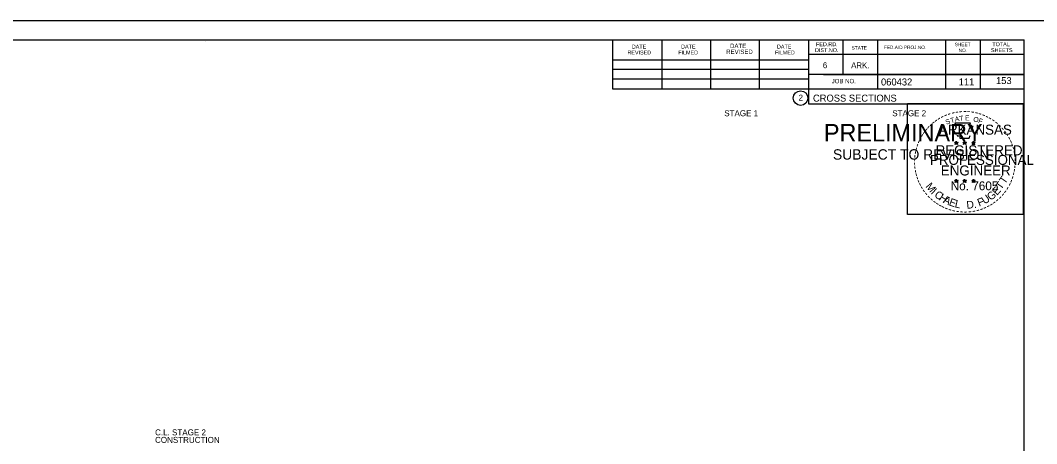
# Model space of a CAD drawing. Extents: x 1538688 to 1540766, y 656250 to 671912.
# Drawn here: x 1538815.6 to 1539018.9, y 664146.7 to 664231.4 of the extents above; entities that cross this region are included whole.
import ezdxf

# ---------------------------------------------------------------- set-up
doc = ezdxf.new("R2010")
doc.units = 0
for name, color, linetype in [('26', 7, 'Continuous'), ('7', 7, 'Continuous'), ('8', 7, 'Continuous'), ('9', 7, 'Continuous'), ('Default', 7, 'Continuous'), ('RipRap', 7, 'Continuous')]:
    doc.layers.add(name, color=color, linetype=linetype)

msp = doc.modelspace()

# ---------------------------------------------------------------- linework, layer by layer
at = {"layer": '26'}
msp.add_line((1538687.78, 664231.4), (1539021.11, 664231.4), dxfattribs=at)
for points in [[(1538687.77, 664231.4), (1539021.11, 664231.4), (1539021.11, 664018.07), (1538687.77, 664018.07)], [(1538993.03, 664214.74), (1539016.13, 664214.74), (1539016.13, 664192.59), (1538993.03, 664192.59)]]:
    msp.add_lwpolyline(points, close=True, dxfattribs=at)
at = {"layer": '8'}
for p, q in [((1539002.44, 664206.95), (1539002.79, 664206.84)), ((1539002.44, 664206.95), (1539002.69, 664206.91)), ((1539002.44, 664206.95), (1539002.68, 664206.83)), ((1539002.57, 664206.55), (1539002.79, 664206.84)), ((1539002.57, 664206.55), (1539002.7, 664206.79)), ((1539002.57, 664206.55), (1539002.79, 664206.76)), ((1539002.79, 664207.21), (1539002.75, 664206.96)), ((1539002.79, 664206.84), (1539002.79, 664207.21)), ((1539002.79, 664207.21), (1539002.84, 664206.96)), ((1539003.13, 664206.95), (1539002.79, 664206.84)), ((1539003, 664206.55), (1539002.79, 664206.84)), ((1539003, 664206.55), (1539002.79, 664206.76)), ((1539003.13, 664206.95), (1539002.85, 664206.91)), ((1539003, 664206.55), (1539002.86, 664206.84)), ((1539003.13, 664206.95), (1539002.93, 664206.85)), ((1539004.11, 664206.95), (1539004.46, 664206.84)), ((1539004.11, 664206.95), (1539004.36, 664206.91)), ((1539004.11, 664206.95), (1539004.35, 664206.83)), ((1539004.24, 664206.55), (1539004.46, 664206.84)), ((1539004.24, 664206.55), (1539004.37, 664206.79)), ((1539004.24, 664206.55), (1539004.46, 664206.76)), ((1539004.46, 664207.21), (1539004.42, 664206.96)), ((1539004.46, 664206.84), (1539004.46, 664207.21)), ((1539004.46, 664207.21), (1539004.51, 664206.96)), ((1539004.8, 664206.95), (1539004.46, 664206.84)), ((1539004.67, 664206.55), (1539004.46, 664206.84)), ((1539004.67, 664206.55), (1539004.46, 664206.76)), ((1539004.8, 664206.95), (1539004.52, 664206.91)), ((1539004.67, 664206.55), (1539004.53, 664206.84)), ((1539004.8, 664206.95), (1539004.6, 664206.85)), ((1539005.87, 664206.94), (1539006.22, 664206.83)), ((1539005.87, 664206.94), (1539006.13, 664206.9)), ((1539005.87, 664206.94), (1539006.11, 664206.82)), ((1539006.01, 664206.53), (1539006.22, 664206.83)), ((1539006.01, 664206.53), (1539006.13, 664206.78)), ((1539006.01, 664206.53), (1539006.22, 664206.75)), ((1539006.22, 664207.2), (1539006.18, 664206.94)), ((1539006.22, 664206.83), (1539006.22, 664207.2)), ((1539006.22, 664207.2), (1539006.27, 664206.95)), ((1539006.57, 664206.94), (1539006.22, 664206.83)), ((1539006.43, 664206.53), (1539006.22, 664206.83)), ((1539006.43, 664206.53), (1539006.22, 664206.75)), ((1539006.57, 664206.94), (1539006.28, 664206.89)), ((1539006.43, 664206.53), (1539006.3, 664206.83)), ((1539006.57, 664206.94), (1539006.36, 664206.84)), ((1539002.43, 664199.38), (1539002.78, 664199.27)), ((1539002.43, 664199.38), (1539002.69, 664199.34)), ((1539002.43, 664199.38), (1539002.67, 664199.26)), ((1539002.57, 664198.97), (1539002.78, 664199.27)), ((1539002.57, 664198.97), (1539002.69, 664199.22)), ((1539002.57, 664198.97), (1539002.78, 664199.19)), ((1539002.78, 664199.64), (1539002.74, 664199.38)), ((1539002.78, 664199.27), (1539002.78, 664199.64)), ((1539002.78, 664199.64), (1539002.83, 664199.39)), ((1539003.13, 664199.38), (1539002.78, 664199.27)), ((1539003, 664198.97), (1539002.78, 664199.27)), ((1539003, 664198.97), (1539002.78, 664199.19)), ((1539003.13, 664199.38), (1539002.84, 664199.33)), ((1539003, 664198.97), (1539002.86, 664199.26)), ((1539003.13, 664199.38), (1539002.93, 664199.28)), ((1539004.1, 664199.38), (1539004.45, 664199.27)), ((1539004.1, 664199.38), (1539004.36, 664199.34)), ((1539004.1, 664199.38), (1539004.34, 664199.26)), ((1539004.24, 664198.97), (1539004.45, 664199.27)), ((1539004.24, 664198.97), (1539004.36, 664199.22)), ((1539004.24, 664198.97), (1539004.45, 664199.19)), ((1539004.45, 664199.64), (1539004.41, 664199.38)), ((1539004.45, 664199.27), (1539004.45, 664199.64)), ((1539004.45, 664199.64), (1539004.5, 664199.39)), ((1539004.8, 664199.38), (1539004.45, 664199.27)), ((1539004.67, 664198.97), (1539004.45, 664199.27)), ((1539004.67, 664198.97), (1539004.45, 664199.19)), ((1539004.8, 664199.38), (1539004.51, 664199.33)), ((1539004.67, 664198.97), (1539004.53, 664199.26)), ((1539004.8, 664199.38), (1539004.6, 664199.28)), ((1539005.87, 664199.37), (1539006.22, 664199.26)), ((1539005.87, 664199.37), (1539006.12, 664199.33)), ((1539005.87, 664199.37), (1539006.11, 664199.25)), ((1539006, 664198.96), (1539006.22, 664199.26)), ((1539006, 664198.96), (1539006.13, 664199.21)), ((1539006, 664198.96), (1539006.22, 664199.18)), ((1539006.22, 664199.63), (1539006.18, 664199.37)), ((1539006.22, 664199.26), (1539006.22, 664199.63)), ((1539006.22, 664199.63), (1539006.27, 664199.38)), ((1539006.57, 664199.37), (1539006.22, 664199.26)), ((1539006.43, 664198.96), (1539006.22, 664199.26)), ((1539006.43, 664198.96), (1539006.22, 664199.18)), ((1539006.57, 664199.37), (1539006.28, 664199.32)), ((1539006.43, 664198.96), (1539006.3, 664199.25)), ((1539006.57, 664199.37), (1539006.36, 664199.27))]:
    msp.add_line(p, q, dxfattribs=at)
for points in [[(1539002.48, 664210.83), (1539002.75, 664210.01)], [(1539005.99, 664209.91), (1539006.13, 664210.19), (1539005.45, 664210.17), (1539005.6, 664210.83), (1539002.48, 664210.83)], [(1539002.97, 664208.41), (1539002.97, 664208.32), (1539003.53, 664208.3), (1539003.48, 664207.83), (1539005.35, 664207.83), (1539005.55, 664208.37)], [(1539002.79, 664207.21), (1539003, 664206.55), (1539002.44, 664206.95), (1539003.13, 664206.95), (1539002.57, 664206.55), (1539002.79, 664207.21)], [(1539004.46, 664207.21), (1539004.67, 664206.55), (1539004.11, 664206.95), (1539004.8, 664206.95), (1539004.24, 664206.55), (1539004.46, 664207.21)], [(1539006.22, 664207.2), (1539006.43, 664206.53), (1539005.87, 664206.94), (1539006.57, 664206.94), (1539006.01, 664206.53), (1539006.22, 664207.2)], [(1539002.78, 664199.64), (1539003, 664198.97), (1539002.43, 664199.38), (1539003.13, 664199.38), (1539002.57, 664198.97), (1539002.78, 664199.64)], [(1539004.45, 664199.64), (1539004.67, 664198.97), (1539004.1, 664199.38), (1539004.8, 664199.38), (1539004.24, 664198.97), (1539004.45, 664199.64)], [(1539006.22, 664199.63), (1539006.43, 664198.96), (1539005.87, 664199.37), (1539006.57, 664199.37), (1539006, 664198.96), (1539006.22, 664199.63)]]:
    msp.add_lwpolyline(points, dxfattribs=at)
for centre, radius in [((1539002.79, 664206.84), 0.172), ((1539002.79, 664206.84), 0.145), ((1539002.79, 664206.84), 0.116), ((1539002.79, 664206.84), 0.0991), ((1539002.79, 664206.84), 0.0747), ((1539002.79, 664206.84), 0.0495), ((1539002.79, 664206.84), 0.0296), ((1539004.46, 664206.84), 0.172), ((1539004.46, 664206.84), 0.145), ((1539004.46, 664206.84), 0.116), ((1539004.46, 664206.84), 0.0991), ((1539004.46, 664206.84), 0.0747), ((1539004.46, 664206.84), 0.0495), ((1539004.46, 664206.84), 0.0296), ((1539006.22, 664206.83), 0.172), ((1539006.22, 664206.83), 0.145), ((1539006.22, 664206.83), 0.116), ((1539006.22, 664206.83), 0.0991), ((1539006.22, 664206.83), 0.0747), ((1539006.22, 664206.83), 0.0495), ((1539006.22, 664206.83), 0.0296), ((1539002.78, 664199.27), 0.172), ((1539002.78, 664199.27), 0.145), ((1539002.78, 664199.27), 0.116), ((1539002.78, 664199.27), 0.0991), ((1539002.78, 664199.27), 0.0747), ((1539002.78, 664199.27), 0.0495), ((1539002.78, 664199.27), 0.0296), ((1539004.45, 664199.27), 0.172), ((1539004.45, 664199.27), 0.145), ((1539004.45, 664199.27), 0.116), ((1539004.45, 664199.27), 0.0991), ((1539004.45, 664199.27), 0.0747), ((1539004.45, 664199.27), 0.0495), ((1539004.45, 664199.27), 0.0296), ((1539006.22, 664199.26), 0.172), ((1539006.22, 664199.26), 0.145), ((1539006.22, 664199.26), 0.116), ((1539006.22, 664199.26), 0.0991), ((1539006.22, 664199.26), 0.0747), ((1539006.22, 664199.26), 0.0495), ((1539006.22, 664199.26), 0.0296)]:
    msp.add_circle(centre, radius, dxfattribs=at)
at = {"layer": 'RipRap'}
for p, q in [((1538700.18, 664227.51), (1539016.36, 664227.51)), ((1538852.7, 664227.25), (1538852.7, 664227.25)), ((1538852.7, 664227.25), (1538852.7, 664227.25)), ((1538934.1, 664217.63), (1538934.1, 664227.51)), ((1538943.96, 664217.63), (1538943.96, 664227.31)), ((1538953.72, 664217.63), (1538953.72, 664227.31)), ((1538963.4, 664217.63), (1538963.4, 664227.31)), ((1538973.26, 664227.51), (1538973.26, 664214.71)), ((1538980.1, 664227.51), (1538980.1, 664220.57)), ((1538987.04, 664227.51), (1538987.04, 664217.63)), ((1539000.62, 664227.51), (1539000.62, 664217.63)), ((1539007.56, 664227.51), (1539007.56, 664217.63)), ((1539016.36, 664022.05), (1539016.36, 664227.51)), ((1539016.36, 664224.59), (1539016.36, 664224.59)), ((1538934.1, 664223.49), (1538973.26, 664223.49)), ((1539016.36, 664224.57), (1538973.26, 664224.57)), ((1538934.1, 664221.63), (1538973.26, 664221.63)), ((1539016.36, 664220.57), (1538973.26, 664220.57)), ((1538976.22, 664220.57), (1539016.36, 664220.57)), ((1538934.1, 664217.63), (1538934.1, 664219.69)), ((1538934.1, 664219.69), (1538973.26, 664219.69)), ((1539016.36, 664217.63), (1538934.1, 664217.63)), ((1538973.26, 664214.71), (1539016.36, 664214.71))]:
    msp.add_line(p, q, dxfattribs=at)
msp.add_circle((1538971.64, 664215.84), 1.47, dxfattribs=at)

# ---------------------------------------------------------------- texts
at = {"layer": '7'}
for s, p in [('111', (1539003.27, 664218.39)), ('153', (1539010.73, 664218.65))]:
    msp.add_text(s, height=1.4, dxfattribs=at).set_placement(p)
at = {"layer": '8'}
for s, height, rotation, p in [('-', 1.6, 24.3072, (1539000.59, 664211.69)), ('-', 1.6, 19.1761, (1539001.23, 664211.96)), ('-', 1.6, 13.6301, (1539001.98, 664212.2)), ('-', 1.6, 10.2193, (1539002.66, 664212.36)), ('-', 1.6, 5.8968, (1539003.38, 664212.47)), ('-', 1.6, 0.1862, (1539004.16, 664212.54)), ('E', 1, 0.8323, (1539004.53, 664211.37)), ('-', 1.6, 357.743, (1539004.88, 664212.53)), ('-', 1.6, 352.1617, (1539005.62, 664212.48)), ('-', 1.6, 347.2049, (1539006.34, 664212.36)), ('-', 1.6, 342.3362, (1539006.98, 664212.21)), ('-', 1.6, 337.8551, (1539007.71, 664211.98)), ('-', 1.6, 42.9622, (1538997.88, 664209.81)), ('-', 1.6, 38.9507, (1538998.31, 664210.23)), ('-', 1.6, 36.2317, (1538998.79, 664210.61)), ('-', 1.6, 34.0636, (1538999.36, 664211)), ('ARKANSAS', 2, 360, (1538999.33, 664208.54)), ('-', 1.6, 28.7918, (1538999.96, 664211.37)), ('S', 1, 21.594, (1539000.83, 664210.51)), ('T', 1, 16.4036, (1539001.75, 664210.84)), ('A', 1, 11.2132, (1539002.57, 664211.09)), ('T', 1, 6.0228, (1539003.42, 664211.26)), ('O', 1, 350.4515, (1539006.13, 664211.16)), ('F', 1, 340.0707, (1539007.09, 664210.93)), ('-', 1.6, 334.1211, (1539008.34, 664211.71)), ('-', 1.6, 329.6409, (1539008.92, 664211.43)), ('-', 1.6, 325.8627, (1539009.57, 664211.07)), ('-', 1.6, 320.5297, (1539010.18, 664210.64)), ('-', 1.6, 315.5786, (1539010.77, 664210.15)), ('-', 1.6, 58.0706, (1538996.29, 664207.76)), ('-', 1.6, 54.2325, (1538996.61, 664208.28)), ('-', 1.6, 50.6142, (1538997.03, 664208.85)), ('-', 1.6, 48.423, (1538997.43, 664209.34)), ('-', 1.6, 309.8797, (1539011.34, 664209.6)), ('-', 1.6, 306.6522, (1539011.87, 664209)), ('-', 1.4, 303.6753, (1539012.35, 664208.43)), ('-', 1.6, 72.3945, (1538995.5, 664205.9)), ('-', 1.6, 67.7743, (1538995.72, 664206.53)), ('-', 1.6, 62.8713, (1538995.97, 664207.14)), ('REGISTERED', 2, 360, (1538998.65, 664204.4)), ('DWB', 0.01, 360, (1539002.77, 664206.84)), ('DWB', 0.01, 360, (1539004.44, 664206.84)), ('DWB', 0.01, 360, (1539006.21, 664206.83)), ('-', 1.6, 299.6684, (1539012.67, 664207.83)), ('-', 1.6, 294.6628, (1539013, 664207.22)), ('-', 1.6, 290.5728, (1539013.25, 664206.64)), ('-', 1.6, 85.1863, (1538995.09, 664203.78)), ('-', 1.6, 81.2013, (1538995.17, 664204.47)), ('-', 1.6, 75.461, (1538995.3, 664205.19)), ('PROFESSIONAL', 2, 360, (1538997.51, 664202.49)), ('-', 1.6, 285.1233, (1539013.49, 664206.06)), ('-', 1.6, 280.5493, (1539013.69, 664205.32)), ('-', 1.6, 276.5962, (1539013.85, 664204.55)), ('-', 1.6, 94.1959, (1538995.1, 664202.36)), ('-', 1.6, 89.0622, (1538995.07, 664203.08)), ('-', 1.6, 98.9479, (1538995.17, 664201.69)), ('ENGINEER', 2, 360, (1538999.69, 664200.37)), ('-', 1.6, 263.5172, (1539013.93, 664202.53)), ('-', 1.6, 274.3301, (1539013.91, 664203.83)), ('-', 1.6, 269.9407, (1539013.94, 664203.19)), ('-', 1.6, 101.7149, (1538995.31, 664200.96)), ('-', 1.6, 105.4578, (1538995.47, 664200.36)), ('T', 1.54, 55.055, (1539012.5, 664198.54)), ('-', 1.6, 252.8681, (1539013.56, 664200.48)), ('-', 1.6, 255.7626, (1539013.74, 664201.2)), ('-', 1.6, 260.9953, (1539013.85, 664201.87)), ('-', 1.6, 109.0874, (1538995.69, 664199.73)), ('-', 1.6, 114.0643, (1538995.94, 664199.13)), ('-', 1.6, 115.7289, (1538996.24, 664198.52)), ('-', 1.6, 120.4471, (1538996.6, 664197.93)), ('M', 1.54, 308.9175, (1538996.55, 664198.16)), ('No. 7605', 1.757, 360, (1539001.67, 664197.42)), ('DWB', 0.01, 360, (1539002.77, 664199.27)), ('DWB', 0.01, 360, (1539004.44, 664199.26)), ('DWB', 0.01, 360, (1539006.2, 664199.26)), ('E', 1.54, 48.7313, (1539010.93, 664196.29)), ('T', 1.54, 55.055, (1539011.77, 664197.42)), ('-', 1.6, 244.6197, (1539013.08, 664199.17)), ('-', 1.6, 247.8887, (1539013.34, 664199.8)), ('-', 1.6, 125.8934, (1538997, 664197.37)), ('-', 1.6, 130.7181, (1538997.47, 664196.82)), ('-', 1.6, 134.2238, (1538997.98, 664196.27)), ('I', 1.54, 316.4636, (1538997.6, 664196.84)), ('C', 1.54, 324.0197, (1538998.27, 664196.22)), ('H', 1.54, 327.5342, (1538999.18, 664195.56)), ('A', 1.54, 332.5513, (1539000.03, 664195.03)), ('U', 1.54, 34.4052, (1539008.47, 664194.54)), ('G', 1.54, 38.2173, (1539009.67, 664195.27)), ('-', 1.6, 225.7653, (1539011.37, 664196.64)), ('-', 1.6, 231.2538, (1539011.85, 664197.2)), ('-', 1.6, 233.8452, (1539012.28, 664197.77)), ('-', 1.6, 239.0712, (1539012.68, 664198.42)), ('-', 1.6, 138.9338, (1538998.51, 664195.81)), ('-', 1.6, 144.6463, (1538999.06, 664195.4)), ('-', 1.6, 148.0898, (1538999.63, 664195.03)), ('-', 1.6, 151.5704, (1539000.2, 664194.71)), ('-', 1.6, 154.6002, (1539000.73, 664194.46)), ('E', 1.54, 339.2068, (1539001.19, 664194.46)), ('L', 1.54, 346.2929, (1539002.38, 664194.04)), ('D.', 1.54, 5.2602, (1539004.89, 664193.7)), ('F', 1.54, 20.8202, (1539007.34, 664194.14)), ('-', 1.6, 204.2516, (1539008.59, 664194.61)), ('-', 1.6, 207.3568, (1539009.21, 664194.93)), ('-', 1.6, 212.2491, (1539009.77, 664195.27)), ('-', 1.6, 215.7363, (1539010.3, 664195.66)), ('-', 1.6, 221.0851, (1539010.85, 664196.13)), ('-', 1.6, 158.5612, (1539001.35, 664194.21)), ('-', 1.6, 162.7983, (1539002.04, 664193.99)), ('-', 1.6, 167.5555, (1539002.75, 664193.83)), ('-', 1.6, 173.1155, (1539003.52, 664193.72)), ('-', 1.6, 176.5183, (1539004.27, 664193.67)), ('-', 1.6, 181.5918, (1539005.02, 664193.68)), ('-', 1.6, 185.8167, (1539005.83, 664193.76)), ('-', 1.6, 191.2858, (1539006.56, 664193.89)), ('-', 1.6, 195.4743, (1539007.29, 664194.09)), ('-', 1.6, 200.7184, (1539007.97, 664194.33))]:
    msp.add_text(s, height=height, rotation=rotation, dxfattribs=at).set_placement(p)
at = {"layer": '9'}
for s, height, p in [('PRELIMINARY', 3.5, (1538976.31, 664207.17)), ('DWB', 0.01, (1538977.06, 664209.02)), ('SUBJECT TO REVISION', 2.0751, (1538978.12, 664203.54))]:
    msp.add_text(s, height=height, rotation=360, dxfattribs=at).set_placement(p)
at = {"layer": 'Default'}
for s, p in [('STAGE 1', (1538956.38, 664212.22)), ('STAGE 2', (1538989.98, 664212.22)), ('C.L. STAGE 2', (1538842.55, 664148.38)), ('CONSTRUCTION', (1538842.54, 664146.88))]:
    msp.add_text(s, height=1.2, dxfattribs=at).set_placement(p)
at = {"layer": 'RipRap'}
for s, height, p in [('DATE', 0.879, (1538957.54, 664225.85)), ('FED.RD.', 0.782, (1538974.74, 664226.23)), ('SHEET', 0.684, (1539002.48, 664226.23)), ('TOTAL', 0.782, (1539010, 664226.23)), ('REVISED', 0.782, (1538937.02, 664224.57)), ('DATE', 0.782, (1538937.9, 664225.75)), ('FILMED', 0.782, (1538947.18, 664224.57)), ('DATE', 0.782, (1538947.76, 664225.75)), ('REVISED', 0.879, (1538956.76, 664224.67)), ('FILMED', 0.782, (1538966.52, 664224.57)), ('DATE', 0.782, (1538966.92, 664225.75)), ('DIST.NO.', 0.782, (1538974.54, 664225.05)), ('STATE', 0.684, (1538981.86, 664225.55)), ('FED.AID PROJ.NO.', 0.684, (1538988.32, 664225.65)), ('NO.', 0.684, (1539003.26, 664225.05)), ('SHEETS', 0.782, (1539009.72, 664225.05)), ('6', 1.17, (1538976.1, 664221.83)), ('ARK.', 1.172, (1538981.76, 664221.83)), ('JOB NO.', 0.879, (1538977.86, 664218.81)), ('060432', 1.4, (1538987.73, 664218.37)), ('2', 1.17, (1538971.26, 664215.36)), ('CROSS SECTIONS', 1.4, (1538974.12, 664215.14))]:
    msp.add_text(s, height=height, rotation=360, dxfattribs=at).set_placement(p)

doc.saveas('drawing.dxf')
